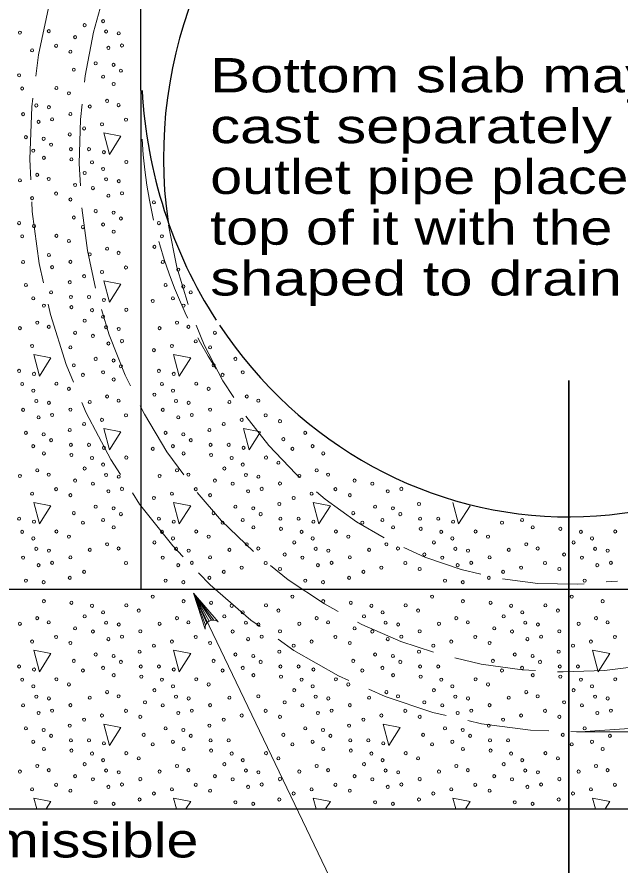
# Model space of a CAD drawing. Extents: x 1083.1 to 1117.1, y 697.4 to 719.4.
# Drawn here: x 1086.546 to 1089.284, y 700.066 to 703.92 of the extents above; entities that cross this region are included whole.
import ezdxf

# ---------------------------------------------------------------- set-up
doc = ezdxf.new("R2010")
doc.units = 0
doc.header["$LTSCALE"] = 0.062
doc.linetypes.add('LONG_DASHED', pattern=[7.5, 6, -1.5])
doc.layers.add('1', color=7, linetype='Continuous', lineweight=13)

msp = doc.modelspace()

# ---------------------------------------------------------------- linework, layer by layer
at = {"layer": '1', "lineweight": 25}
for p, q in [((1087.10775, 703.58592), (1087.10775, 706.14442)), ((1087.10775, 703.58592), (1087.10775, 701.31858)), ((1086.25067, 701.31858), (1091.86725, 701.31858))]:
    msp.add_line(p, q, dxfattribs=at)
at = {"layer": '1'}
for p, q in [((1088.52558, 701.71342), (1088.55125, 701.61608)), ((1088.55125, 701.61608), (1088.6035, 701.69825)), ((1087.41833, 701.17433), (1087.3475, 701.30158)), ((1087.40767, 701.16533), (1087.3475, 701.30158)), ((1087.40192, 701.1555), (1087.3475, 701.30158)), ((1087.4285, 701.17825), (1087.3475, 701.30158)), ((1087.44025, 701.17883), (1087.3475, 701.30158)), ((1092.31558, 700.67117), (1089.08633, 700.67117)), ((1086.62233, 700.37008), (1086.63525, 700.32125)), ((1087.25683, 700.37008), (1087.26958, 700.32125)), ((1087.33467, 700.355), (1087.25683, 700.37008)), ((1087.31317, 700.32125), (1087.33467, 700.355)), ((1087.89117, 700.37008), (1087.90408, 700.32125)), ((1087.969, 700.355), (1087.89117, 700.37008)), ((1087.94758, 700.32125), (1087.969, 700.355)), ((1088.52558, 700.37008), (1088.5385, 700.32133)), ((1088.6035, 700.355), (1088.52558, 700.37008)), ((1088.582, 700.32125), (1088.6035, 700.355)), ((1089.16, 700.37008), (1089.17292, 700.32133)), ((1089.23783, 700.355), (1089.16, 700.37008)), ((1089.2165, 700.32133), (1089.23783, 700.355))]:
    msp.add_line(p, q, dxfattribs=at)
at = {"layer": '1', "lineweight": 25}
msp.add_lwpolyline([(1086.25067, 706.14383), (1086.25067, 700.32125), (1091.86725, 700.32125)], dxfattribs=at)
at = {"layer": '1'}
for points in [[(1086.93958, 703.3925), (1086.96525, 703.29525), (1087.0175, 703.37742)], [(1086.93958, 702.72092), (1086.96525, 702.6235), (1087.0175, 702.70567)], [(1086.62233, 702.385), (1086.648, 702.28775), (1086.70025, 702.36992)], [(1087.25683, 702.385), (1087.2825, 702.28775), (1087.33467, 702.36992)], [(1086.93958, 702.04925), (1086.96525, 701.95192), (1087.0175, 702.03408)], [(1087.574, 702.04925), (1087.59958, 701.95192), (1087.65192, 702.03408)], [(1086.62233, 701.71342), (1086.648, 701.61608), (1086.70025, 701.69825)], [(1087.25683, 701.71342), (1087.2825, 701.61608), (1087.33467, 701.69825)], [(1087.89117, 701.71342), (1087.91683, 701.61608), (1087.969, 701.69825)], [(1086.62233, 701.04175), (1086.648, 700.94442), (1086.70025, 701.02658)], [(1087.25683, 701.04175), (1087.2825, 700.94442), (1087.33467, 701.02658)], [(1089.16, 701.04175), (1089.18558, 700.94442), (1089.23783, 701.02658)], [(1086.93958, 700.70592), (1086.96525, 700.60858), (1087.0175, 700.69075)], [(1088.20842, 700.70592), (1088.234, 700.60858), (1088.28625, 700.69075)]]:
    msp.add_lwpolyline(points, close=True, dxfattribs=at)
at = {"layer": '1', "lineweight": 35}
msp.add_lwpolyline([(1089.05217, 702.26792), (1089.05217, 699.87742), (1089.05217, 699.45117)], dxfattribs=at)
at = {"layer": '1'}
for points in [[(1087.39992, 701.13825), (1087.3475, 701.30158), (1087.45875, 701.17092)], [(1087.3475, 701.30158), (1088.001, 699.937), (1087.65383, 699.937)], [(1086.67883, 700.32125), (1086.70025, 700.355), (1086.62233, 700.37008)]]:
    msp.add_lwpolyline(points, dxfattribs=at)
msp.add_arc((1087.43598, 701.14272), 0.03631, 51.19607, 187.0222, dxfattribs=at)
at = {"layer": '1', "lineweight": 25}
for centre, major_axis, start_param, end_param in [((1089.04277, 703.2802), (0, 1.93921), 4.5449685, 8.0045958), ((1089.0514, 703.70217), (0, 2.05412), 1.6274315, 2.1709306), ((1089.0514, 703.70217), (0, 2.05412), 2.1841627, 4.1070394)]:
    msp.add_ellipse(centre, major_axis=major_axis, ratio=0.944544, start_param=start_param, end_param=end_param, dxfattribs=at)
at = {"layer": '1', "linetype": 'LONG_DASHED'}
for centre, major_axis, start_param, end_param in [((1089.06894, 703.28095), (0, -2.60983), 4.0615652, 8.5327307), ((1089.04094, 703.28499), (0, -2.34206), 4.204739, 8.3489001), ((1089.05133, 703.47998), (0, 2.05412), 1.6274315, 2.1709306), ((1089.04277, 703.2802), (0, 1.93921), 1.7298013, 3.267729)]:
    msp.add_ellipse(centre, major_axis=major_axis, ratio=0.944544, start_param=start_param, end_param=end_param, dxfattribs=at)
at = {"layer": '1'}
for centre in [(1086.8531, 703.88245), (1086.93705, 703.90058), (1086.55905, 703.84864), (1086.69011, 703.85497), (1086.9508, 703.85345), (1087.00816, 703.84523), (1086.81001, 703.82776), (1086.61472, 703.76787), (1086.72347, 703.78875), (1086.961, 703.77907), (1087.0227, 703.78998), (1086.7886, 703.76155), (1086.90338, 703.70899), (1086.98421, 703.702), (1086.55567, 703.65453), (1086.80404, 703.67994), (1087.01788, 703.67541), (1086.93679, 703.64821), (1086.98505, 703.61524), (1086.56936, 703.5947), (1086.72521, 703.59649), (1086.78173, 703.57293), (1086.95508, 703.53817), (1086.6336, 703.51763), (1086.69096, 703.5094), (1086.87625, 703.51282), (1087.00731, 703.51914), (1086.57359, 703.47772), (1086.7886, 703.47856), (1086.6438, 703.44324), (1086.70549, 703.45416), (1086.93192, 703.43205), (1087.04067, 703.45293), (1086.78548, 703.38582), (1086.85051, 703.41302), (1086.58617, 703.37317), (1086.66701, 703.36617), (1086.61959, 703.31238), (1086.70068, 703.33959), (1086.79061, 703.31871), (1086.87287, 703.31871), (1086.94049, 703.30511), (1086.66785, 703.27942), (1086.79315, 703.27248), (1086.88656, 703.25888), (1086.93705, 703.22893), (1087.04241, 703.26067), (1086.63788, 703.20235), (1086.8531, 703.2108), (1086.55905, 703.17699), (1086.69011, 703.18332), (1086.81001, 703.15611), (1086.9508, 703.1818), (1087.00816, 703.17358), (1086.72347, 703.1171), (1086.89079, 703.1419), (1087.0227, 703.11833), (1086.61472, 703.09623), (1086.7886, 703.0899), (1086.961, 703.10742), (1087.16771, 703.0772), (1086.90338, 703.03734), (1086.80404, 703.0083), (1086.98421, 703.03035), (1087.01788, 703.00376), (1086.55567, 702.98288), (1086.62329, 702.96928), (1086.84517, 702.96475), (1086.93679, 702.97656), (1087.19007, 702.98288), (1086.56936, 702.92305), (1086.72521, 702.92484), (1086.98505, 702.94359), (1087.20376, 702.92305), (1086.78173, 702.90128), (1086.95508, 702.86652), (1087.00731, 702.84749), (1087.1703, 702.87497), (1086.57359, 702.80607), (1086.69096, 702.83775), (1086.7886, 702.80691), (1086.87625, 702.84117), (1087.20799, 702.80607), (1086.70549, 702.78251), (1087.04067, 702.78128), (1087.2782, 702.7716), (1086.85051, 702.74137), (1086.93192, 702.7604), (1086.58617, 702.70152), (1086.78548, 702.71417), (1087.22058, 702.70152), (1087.30141, 702.69452), (1086.70068, 702.66794), (1087.33509, 702.66794), (1086.61959, 702.64074), (1086.79061, 702.64706), (1086.87287, 702.64706), (1086.94049, 702.63346), (1087.16237, 702.62893), (1087.25399, 702.64074), (1086.66785, 702.60777), (1086.79315, 702.60083), (1086.88656, 702.58723), (1087.04241, 702.58902), (1087.30226, 702.60777), (1086.8531, 702.53915), (1086.93705, 702.55728), (1086.55905, 702.50534), (1086.63788, 702.5307), (1086.69011, 702.51167), (1086.9508, 702.51016), (1087.00816, 702.50193), (1087.19346, 702.50534), (1087.27228, 702.5307), (1087.32451, 702.51167), (1086.81001, 702.48447), (1086.89079, 702.47025), (1087.44441, 702.48447), (1086.61472, 702.42458), (1086.7886, 702.41825), (1086.961, 702.43577), (1087.0227, 702.44668), (1087.24912, 702.42458), (1087.35787, 702.44545), (1087.423, 702.41825), (1087.16771, 702.40555), (1086.90338, 702.3657), (1086.98421, 702.3587), (1087.53778, 702.3657), (1086.55567, 702.31124), (1086.80404, 702.33665), (1086.93679, 702.30491), (1087.01788, 702.33211), (1087.19007, 702.31124), (1087.43844, 702.33665), (1087.57119, 702.30491), (1086.62329, 702.29763), (1086.84517, 702.2931), (1086.98505, 702.27194), (1087.25769, 702.29763), (1087.47957, 702.2931), (1086.56936, 702.2514), (1086.72521, 702.25319), (1086.78173, 702.22963), (1087.20376, 702.2514), (1087.35962, 702.25319), (1087.41613, 702.22963), (1086.61985, 702.22146), (1086.95508, 702.19487), (1087.1703, 702.20332), (1087.25425, 702.22146), (1087.58948, 702.19487), (1086.6336, 702.17433), (1086.69096, 702.1661), (1086.87625, 702.16952), (1087.00731, 702.17584), (1087.268, 702.17433), (1087.32536, 702.1661), (1087.51066, 702.16952), (1087.64171, 702.17584), (1086.57359, 702.13442), (1086.70549, 702.11086), (1086.7886, 702.13526), (1087.04067, 702.10963), (1087.20799, 702.13442), (1087.3399, 702.11086), (1087.423, 702.13526), (1087.67507, 702.10963), (1086.6438, 702.09995), (1086.93192, 702.08875), (1087.2782, 702.09995), (1087.56633, 702.08875), (1087.7402, 702.08243), (1086.78548, 702.04252), (1086.85051, 702.06972), (1087.41988, 702.04252), (1087.48491, 702.06972), (1086.58617, 702.02987), (1086.66701, 702.02287), (1086.70068, 701.99629), (1087.22058, 702.02987), (1087.30141, 702.02287), (1087.33509, 701.99629), (1087.75564, 702.00082), (1087.85498, 702.02987), (1086.61959, 701.96909), (1086.79061, 701.97541), (1086.87287, 701.97541), (1086.94049, 701.96181), (1087.16237, 701.95728), (1087.25399, 701.96909), (1087.42501, 701.97541), (1087.50727, 701.97541), (1087.57489, 701.96181), (1087.79677, 701.95728), (1087.88839, 701.96909), (1086.66785, 701.93612), (1086.79315, 701.92918), (1087.04241, 701.91737), (1087.30226, 701.93612), (1087.42755, 701.92918), (1087.67682, 701.91737), (1087.93666, 701.93612), (1086.88656, 701.91558), (1086.93705, 701.88563), (1087.52097, 701.91558), (1087.57145, 701.88563), (1087.73333, 701.89381), (1086.63788, 701.85905), (1086.69011, 701.84002), (1086.8531, 701.8675), (1087.27228, 701.85905), (1087.32451, 701.84002), (1087.4875, 701.8675), (1087.90668, 701.85905), (1087.95891, 701.84002), (1086.55905, 701.83369), (1086.81001, 701.81282), (1086.9508, 701.83851), (1087.00816, 701.83028), (1087.19346, 701.83369), (1087.44441, 701.81282), (1087.5852, 701.83851), (1087.64256, 701.83028), (1087.82786, 701.83369), (1088.07882, 701.81282), (1086.72347, 701.7738), (1086.89079, 701.7986), (1086.961, 701.76412), (1087.0227, 701.77504), (1087.35787, 701.7738), (1087.52519, 701.7986), (1087.5954, 701.76412), (1087.6571, 701.77504), (1087.7402, 701.79944), (1087.99227, 701.7738), (1088.1596, 701.7986), (1088.2298, 701.76412), (1088.2915, 701.77504), (1086.61472, 701.75293), (1086.7886, 701.7466), (1087.16771, 701.7339), (1087.24912, 701.75293), (1087.423, 701.7466), (1087.80211, 701.7339), (1087.88353, 701.75293), (1088.05741, 701.7466), (1086.90338, 701.69405), (1086.98421, 701.68705), (1087.53778, 701.69405), (1087.61861, 701.68705), (1087.73709, 701.7067), (1088.17218, 701.69405), (1088.25301, 701.68705), (1088.37149, 701.7067), (1086.80404, 701.665), (1087.01788, 701.66046), (1087.43844, 701.665), (1087.65229, 701.66046), (1088.07284, 701.665), (1088.28669, 701.66046), (1086.55567, 701.63959), (1086.62329, 701.62599), (1086.84517, 701.62145), (1086.93679, 701.63326), (1087.19007, 701.63959), (1087.25769, 701.62599), (1087.47957, 701.62145), (1087.57119, 701.63326), (1087.74221, 701.63959), (1087.82447, 701.63959), (1087.89209, 701.62599), (1088.11397, 701.62145), (1088.20559, 701.63326), (1088.37662, 701.63959), (1088.45888, 701.63959), (1088.52649, 701.62599), (1088.74837, 701.62145), (1088.83999, 701.63326), (1086.56936, 701.57975), (1086.72521, 701.58154), (1086.98505, 701.60029), (1087.20376, 701.57975), (1087.35962, 701.58154), (1087.61946, 701.60029), (1087.74475, 701.59335), (1087.83817, 701.57975), (1087.99402, 701.58154), (1088.25386, 701.60029), (1088.37915, 701.59335), (1088.47257, 701.57975), (1088.62842, 701.58154), (1088.88826, 701.60029), (1089.01355, 701.59335), (1089.10697, 701.57975), (1089.26282, 701.58154), (1086.61985, 701.54981), (1086.78173, 701.55798), (1087.1703, 701.53167), (1087.25425, 701.54981), (1087.41613, 701.55798), (1087.8047, 701.53167), (1087.88865, 701.54981), (1088.05053, 701.55798), (1088.4391, 701.53167), (1088.52306, 701.54981), (1088.68493, 701.55798), (1089.07351, 701.53167), (1089.15746, 701.54981), (1086.6336, 701.50268), (1086.69096, 701.49445), (1086.87625, 701.49787), (1086.95508, 701.52322), (1087.00731, 701.50419), (1087.268, 701.50268), (1087.32536, 701.49445), (1087.51066, 701.49787), (1087.58948, 701.52322), (1087.64171, 701.50419), (1087.9024, 701.50268), (1087.95976, 701.49445), (1088.14506, 701.49787), (1088.22388, 701.52322), (1088.27612, 701.50419), (1088.5368, 701.50268), (1088.59416, 701.49445), (1088.77946, 701.49787), (1088.85828, 701.52322), (1088.91052, 701.50419), (1089.1712, 701.50268), (1089.22856, 701.49445), (1086.57359, 701.46277), (1086.7886, 701.46361), (1087.20799, 701.46277), (1087.423, 701.46361), (1087.76162, 701.47699), (1087.8424, 701.46277), (1088.05741, 701.46361), (1088.39602, 701.47699), (1088.4768, 701.46277), (1088.69181, 701.46361), (1089.03042, 701.47699), (1089.1112, 701.46277), (1086.6438, 701.4283), (1086.70549, 701.43921), (1087.04067, 701.43798), (1087.2782, 701.4283), (1087.3399, 701.43921), (1087.56633, 701.4171), (1087.67507, 701.43798), (1087.9126, 701.4283), (1087.9743, 701.43921), (1088.20073, 701.4171), (1088.30947, 701.43798), (1088.54701, 701.4283), (1088.6087, 701.43921), (1088.83513, 701.4171), (1088.94388, 701.43798), (1089.18141, 701.4283), (1089.2431, 701.43921), (1086.85051, 701.39807), (1087.48491, 701.39807), (1087.7402, 701.41078), (1088.11931, 701.39807), (1088.37461, 701.41078), (1088.75371, 701.39807), (1089.00901, 701.41078), (1086.58617, 701.35822), (1086.66701, 701.35123), (1086.78548, 701.37087), (1087.22058, 701.35822), (1087.30141, 701.35123), (1087.41988, 701.37087), (1087.85498, 701.35822), (1087.93581, 701.35123), (1088.05429, 701.37087), (1088.48938, 701.35822), (1088.57021, 701.35123), (1088.68869, 701.37087), (1089.12378, 701.35822), (1086.66785, 701.26447), (1087.16237, 701.28563), (1087.30226, 701.26447), (1087.79677, 701.28563), (1087.93666, 701.26447), (1088.43117, 701.28563), (1088.57106, 701.26447), (1089.06558, 701.28563), (1089.20546, 701.26447), (1086.79315, 701.25753), (1086.88656, 701.24393), (1087.04241, 701.24572), (1087.42755, 701.25753), (1087.52097, 701.24393), (1087.67682, 701.24572), (1088.06195, 701.25753), (1088.15537, 701.24393), (1088.31122, 701.24572), (1088.69635, 701.25753), (1088.78977, 701.24393), (1088.94562, 701.24572), (1086.63788, 701.1874), (1086.8531, 701.19585), (1086.93705, 701.21398), (1087.09893, 701.22216), (1087.27228, 701.1874), (1087.4875, 701.19585), (1087.57145, 701.21398), (1087.73333, 701.22216), (1087.90668, 701.1874), (1088.1219, 701.19585), (1088.20586, 701.21398), (1088.36773, 701.22216), (1088.54108, 701.1874), (1088.7563, 701.19585), (1088.84026, 701.21398), (1089.00214, 701.22216), (1089.17549, 701.1874), (1086.55905, 701.16204), (1086.69011, 701.16837), (1086.9508, 701.16686), (1087.00816, 701.15863), (1087.19346, 701.16204), (1087.32451, 701.16837), (1087.5852, 701.16686), (1087.64256, 701.15863), (1087.82786, 701.16204), (1087.95891, 701.16837), (1088.2196, 701.16686), (1088.27696, 701.15863), (1088.46226, 701.16204), (1088.59332, 701.16837), (1088.854, 701.16686), (1088.91136, 701.15863), (1089.09666, 701.16204), (1089.22772, 701.16837), (1086.81001, 701.14117), (1086.89079, 701.12695), (1087.1058, 701.12779), (1087.52519, 701.12695), (1087.7402, 701.12779), (1088.07882, 701.14117), (1088.1596, 701.12695), (1088.37461, 701.12779), (1088.71322, 701.14117), (1088.794, 701.12695), (1089.00901, 701.12779), (1086.61472, 701.08128), (1086.72347, 701.10216), (1086.7886, 701.07495), (1086.961, 701.09247), (1087.0227, 701.10339), (1087.24912, 701.08128), (1087.35787, 701.10216), (1087.423, 701.07495), (1087.5954, 701.09247), (1087.6571, 701.10339), (1087.88353, 701.08128), (1087.99227, 701.10216), (1088.05741, 701.07495), (1088.2298, 701.09247), (1088.2915, 701.10339), (1088.51793, 701.08128), (1088.62668, 701.10216), (1088.69181, 701.07495), (1088.86421, 701.09247), (1088.9259, 701.10339), (1089.15233, 701.08128), (1089.26108, 701.10216), (1087.10268, 701.03505), (1087.16771, 701.06225), (1087.73709, 701.03505), (1087.80211, 701.06225), (1088.37149, 701.03505), (1088.43651, 701.06225), (1089.00589, 701.03505), (1089.07092, 701.06225), (1086.80404, 700.99335), (1086.90338, 701.0224), (1086.98421, 701.0154), (1087.43844, 700.99335), (1087.53778, 701.0224), (1087.61861, 701.0154), (1088.07284, 700.99335), (1088.17218, 701.0224), (1088.25301, 701.0154), (1088.70724, 700.99335), (1088.80658, 701.0224), (1088.88741, 701.0154), (1086.55567, 700.96794), (1086.62329, 700.95434), (1086.93679, 700.96161), (1087.01788, 700.98881), (1087.10781, 700.96794), (1087.19007, 700.96794), (1087.25769, 700.95434), (1087.57119, 700.96161), (1087.65229, 700.98881), (1087.74221, 700.96794), (1087.82447, 700.96794), (1087.89209, 700.95434), (1088.20559, 700.96161), (1088.28669, 700.98881), (1088.37662, 700.96794), (1088.45888, 700.96794), (1088.83999, 700.96161), (1088.92109, 700.98881), (1089.01102, 700.96794), (1089.09328, 700.96794), (1086.84517, 700.9498), (1086.98505, 700.92865), (1087.11035, 700.92171), (1087.47957, 700.9498), (1087.61946, 700.92865), (1087.74475, 700.92171), (1088.11397, 700.9498), (1088.25386, 700.92865), (1088.37915, 700.92171), (1088.74837, 700.9498), (1088.88826, 700.92865), (1089.01355, 700.92171), (1086.56936, 700.9081), (1086.61985, 700.87816), (1086.72521, 700.9099), (1086.78173, 700.88633), (1087.20376, 700.9081), (1087.25425, 700.87816), (1087.35962, 700.9099), (1087.41613, 700.88633), (1087.83817, 700.9081), (1087.88865, 700.87816), (1087.99402, 700.9099), (1088.05053, 700.88633), (1088.47257, 700.9081), (1088.52306, 700.87816), (1088.62842, 700.9099), (1088.68493, 700.88633), (1089.10697, 700.9081), (1089.15746, 700.87816), (1089.26282, 700.9099), (1086.95508, 700.85157), (1087.1703, 700.86003), (1087.8047, 700.86003), (1088.22388, 700.85157), (1088.4391, 700.86003), (1088.85828, 700.85157), (1089.07351, 700.86003), (1086.6336, 700.83103), (1086.69096, 700.82281), (1086.87625, 700.82622), (1087.00731, 700.83254), (1087.12721, 700.80534), (1087.268, 700.83103), (1087.32536, 700.82281), (1087.51066, 700.82622), (1087.64171, 700.83254), (1087.76162, 700.80534), (1087.9024, 700.83103), (1087.95976, 700.82281), (1088.14506, 700.82622), (1088.27612, 700.83254), (1088.39602, 700.80534), (1088.5368, 700.83103), (1088.59416, 700.82281), (1088.77946, 700.82622), (1088.91052, 700.83254), (1089.03042, 700.80534), (1089.1712, 700.83103), (1089.22856, 700.82281), (1086.57359, 700.79113), (1086.70549, 700.76756), (1086.7886, 700.79197), (1087.04067, 700.76633), (1087.20799, 700.79113), (1087.3399, 700.76756), (1087.423, 700.79197), (1087.67507, 700.76633), (1087.8424, 700.79113), (1087.9743, 700.76756), (1088.05741, 700.79197), (1088.30947, 700.76633), (1088.4768, 700.79113), (1088.6087, 700.76756), (1088.69181, 700.79197), (1088.94388, 700.76633), (1089.1112, 700.79113), (1089.2431, 700.76756), (1086.6438, 700.75665), (1086.85051, 700.72642), (1086.93192, 700.74545), (1087.1058, 700.73913), (1087.2782, 700.75665), (1087.48491, 700.72642), (1087.56633, 700.74545), (1087.7402, 700.73913), (1087.9126, 700.75665), (1088.11931, 700.72642), (1088.20073, 700.74545), (1088.37461, 700.73913), (1088.54701, 700.75665), (1088.75371, 700.72642), (1088.83513, 700.74545), (1089.00901, 700.73913), (1089.18141, 700.75665), (1086.58617, 700.68657), (1086.78548, 700.69922), (1087.22058, 700.68657), (1087.41988, 700.69922), (1087.85498, 700.68657), (1088.05429, 700.69922), (1088.48938, 700.68657), (1088.68869, 700.69922), (1089.12378, 700.68657), (1086.66701, 700.67958), (1086.70068, 700.65299), (1087.12124, 700.65752), (1087.30141, 700.67958), (1087.33509, 700.65299), (1087.75564, 700.65752), (1087.93581, 700.67958), (1087.96949, 700.65299), (1088.39004, 700.65752), (1088.57021, 700.67958), (1088.60389, 700.65299), (1089.02445, 700.65752), (1089.23829, 700.65299), (1086.61959, 700.62579), (1086.79061, 700.63211), (1086.87287, 700.63211), (1086.94049, 700.61851), (1087.16237, 700.61398), (1087.25399, 700.62579), (1087.42501, 700.63211), (1087.50727, 700.63211), (1087.79677, 700.61398), (1087.88839, 700.62579), (1088.05941, 700.63211), (1088.14167, 700.63211), (1088.20929, 700.61851), (1088.43117, 700.61398), (1088.52279, 700.62579), (1088.69382, 700.63211), (1088.77608, 700.63211), (1089.06558, 700.61398), (1089.15719, 700.62579), (1086.66785, 700.59282), (1086.79315, 700.58588), (1086.88656, 700.57228), (1087.04241, 700.57407), (1087.30226, 700.59282), (1087.42755, 700.58588), (1087.52097, 700.57228), (1087.67682, 700.57407), (1087.93666, 700.59282), (1088.06195, 700.58588), (1088.15537, 700.57228), (1088.31122, 700.57407), (1088.57106, 700.59282), (1088.69635, 700.58588), (1088.78977, 700.57228), (1088.94562, 700.57407), (1089.20546, 700.59282), (1086.93705, 700.54234), (1087.09893, 700.55051), (1087.57145, 700.54234), (1087.73333, 700.55051), (1088.20586, 700.54234), (1088.36773, 700.55051), (1088.84026, 700.54234), (1089.00214, 700.55051), (1086.63788, 700.51575), (1086.69011, 700.49672), (1086.8531, 700.5242), (1086.9508, 700.49521), (1087.27228, 700.51575), (1087.32451, 700.49672), (1087.4875, 700.5242), (1087.5852, 700.49521), (1087.90668, 700.51575), (1087.95891, 700.49672), (1088.1219, 700.5242), (1088.2196, 700.49521), (1088.54108, 700.51575), (1088.59332, 700.49672), (1088.7563, 700.5242), (1088.854, 700.49521), (1089.17549, 700.51575), (1089.22772, 700.49672), (1086.55905, 700.49039), (1086.81001, 700.46952), (1086.89079, 700.4553), (1087.00816, 700.48698), (1087.1058, 700.45614), (1087.19346, 700.49039), (1087.44441, 700.46952), (1087.52519, 700.4553), (1087.64256, 700.48698), (1087.7402, 700.45614), (1087.82786, 700.49039), (1088.07882, 700.46952), (1088.1596, 700.4553), (1088.27696, 700.48698), (1088.37461, 700.45614), (1088.46226, 700.49039), (1088.71322, 700.46952), (1088.794, 700.4553), (1088.91136, 700.48698), (1089.00901, 700.45614), (1089.09666, 700.49039), (1086.72347, 700.43051), (1086.961, 700.42082), (1087.0227, 700.43174), (1087.35787, 700.43051), (1087.5954, 700.42082), (1087.6571, 700.43174), (1087.99227, 700.43051), (1088.2298, 700.42082), (1088.2915, 700.43174), (1088.62668, 700.43051), (1088.86421, 700.42082), (1088.9259, 700.43174), (1089.26108, 700.43051), (1086.61472, 700.40963), (1086.7886, 700.4033), (1087.16771, 700.3906), (1087.24912, 700.40963), (1087.423, 700.4033), (1087.80211, 700.3906), (1087.88353, 700.40963), (1088.05741, 700.4033), (1088.43651, 700.3906), (1088.51793, 700.40963), (1088.69181, 700.4033), (1089.07092, 700.3906), (1089.15233, 700.40963), (1086.90338, 700.35075), (1086.98421, 700.34375), (1087.10268, 700.3634), (1087.53778, 700.35075), (1087.61861, 700.34375), (1087.73709, 700.3634), (1088.17218, 700.35075), (1088.25301, 700.34375), (1088.37149, 700.3634), (1088.80658, 700.35075), (1088.88741, 700.34375), (1089.00589, 700.3634)]:
    msp.add_ellipse(centre, major_axis=(0, 0.00718), ratio=0.944544, dxfattribs=at)

# ---------------------------------------------------------------- texts
for s, width, p in [('Bottom slab may be pre-', 1.3, (1087.4235, 703.57683)), ('cast separately and the', 1.3, (1087.4235, 703.34608)), ('outlet pipe placed on', 1.25, (1087.4235, 703.11533)), ('top of it with the bottom', 1.25, (1087.4235, 702.88458)), ('shaped to drain', 1.3, (1087.4235, 702.65383)), ('Permissible', 1.25, (1086.02217, 700.1))]:
    msp.add_text(s, height=0.156, dxfattribs=dict(at, width=width)).set_placement(p)

doc.saveas('drawing.dxf')
